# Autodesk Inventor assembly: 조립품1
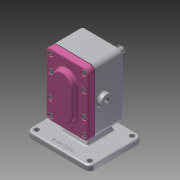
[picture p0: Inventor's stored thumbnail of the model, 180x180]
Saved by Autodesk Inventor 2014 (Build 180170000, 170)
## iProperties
Created: 2020-04
Part Number: 조립품1
Document SubType Name: Assembly
Designer: kh
Author: kh
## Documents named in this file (11)
- C:\Users\kh\Desktop\700407V1023\조립품1.iam
- C:\Users\kh\Desktop\700407V1023\본체.ipt
- C:\Users\kh\Desktop\700407V1023\개스킷.ipt
- C:\Users\kh\Desktop\700407V1023\메인축.ipt
- C:\Users\kh\Desktop\700407V1023\베어링부시.ipt
- C:\Users\kh\Desktop\700407V1023\볼트 M5.ipt
- C:\Users\kh\Desktop\700407V1023\서브축.ipt
- C:\Users\kh\Desktop\700407V1023\스퍼기어.ipt
- C:\Users\kh\Desktop\700407V1023\오일 실 16 28 7.ipt
- C:\Users\kh\Desktop\700407V1023\커버.ipt
- C:\Users\kh\Desktop\700407V1023\키 6 x 6 x 18.ipt
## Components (1 placed, 1 different names)
1. 개스킷:1
